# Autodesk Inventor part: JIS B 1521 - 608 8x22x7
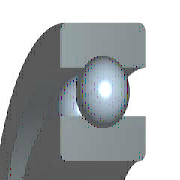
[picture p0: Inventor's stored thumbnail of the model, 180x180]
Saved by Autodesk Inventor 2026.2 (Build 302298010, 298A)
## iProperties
Created: 2025-01
Part Number: JIS B 1521 - 608 8x22x7
Material: 강철, 연강
Description: 깊은 그루부 볼 베어링
Document SubType Name: Modeling
Standard: JIS B 1521
Designer: work
Standard Revision: 2012
Standards Organization: JIS
Language: ko-KR
Size Designation: 608 8x22x7
Categories: <MemberInstance><Categories><Category DisplayName="샤프트 부품" InternalName="7f7aeb1f-a693-4053-b835-cee3144e0d98" Mnemonic="SHFT"><Category DisplayName="베어링" Inter
Density: 7.85 g/cm^3
Appearance: 반연마
IsCustomPart: 1
Author: work
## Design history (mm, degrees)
revolve "본체" stored, may be unused: angle "d6" = 90 deg
revolve "볼" stored, may be unused: angle "d7" = 90 deg
pattern_circular "IDS_ARRAYBALL[SIMPL:T]" dims angle "d3" = 360 deg
body "Solid1"
sketch "스케치" dims "d0" = 3.64 (= -0.26 x WD + 0.26 x BD)
  geometry: L1 (1.68, 7.5)-(5.32, 7.5); L2 (3.5, 7.5)-(3.5, 5.68); L3 (3.5, 7.5)-(3.5, 9.32); L4 (2.148, 6.282)-(0, 6.282); L5 (0, 4)-(7, 4); L6 (2.148, 8.718)-(0, 8.718); L7 (0, 11)-(7, 11); L8 (7, 4)-(7, 6.282); L9 (4.852, 6.282)-(7, 6.282); L10 (4.852, 8.718)-(7, 8.718); L11 (7, 11)-(7, 8.718); L12 (-1.4, 0)-(8.4, 0) reference; L13 (0, -0.3)-(0, 5.3) reference
  constraints: 22 end point, 4 point on line, 2 collinear, 2 perpendicular, 2 symmetric about line, 1 midpoint, 1 parallel, 14 other
  dimensions: "d9" = 8 diameter of L5 L12 (= WD); "d11" = 22 diameter of L7 L12 (= BD); "d12" = 7 distance between parallel lines of L8 L13 (= KB); "d13" = 12.564 diameter of L9 L12 (= 0.326 x BD + 0.674 x WD)
fillet "모깎기1" dims "d1" = 0.3 (= KRS)
other parameters: "WD" = 8 [user parameter; used in 5 equation terms], "BD" = 22 [user parameter; used in 5 equation terms], "KB" = 7 [user parameter; used in 1 equation term], "KRS" = 0.3 [user parameter; used in 1 equation term], "d4" = 0, "d5" = 0, "d8" = 0, "d14" = 0, "d15" = 0, "BBA" = 0 [user parameter], "BC0" = 1370000 [user parameter], "BC" = 3300000 [user parameter], "BR" = 11 (= 0.5 x BD) [user parameter], "WR" = 4 (= 0.5 x WD) [user parameter]
